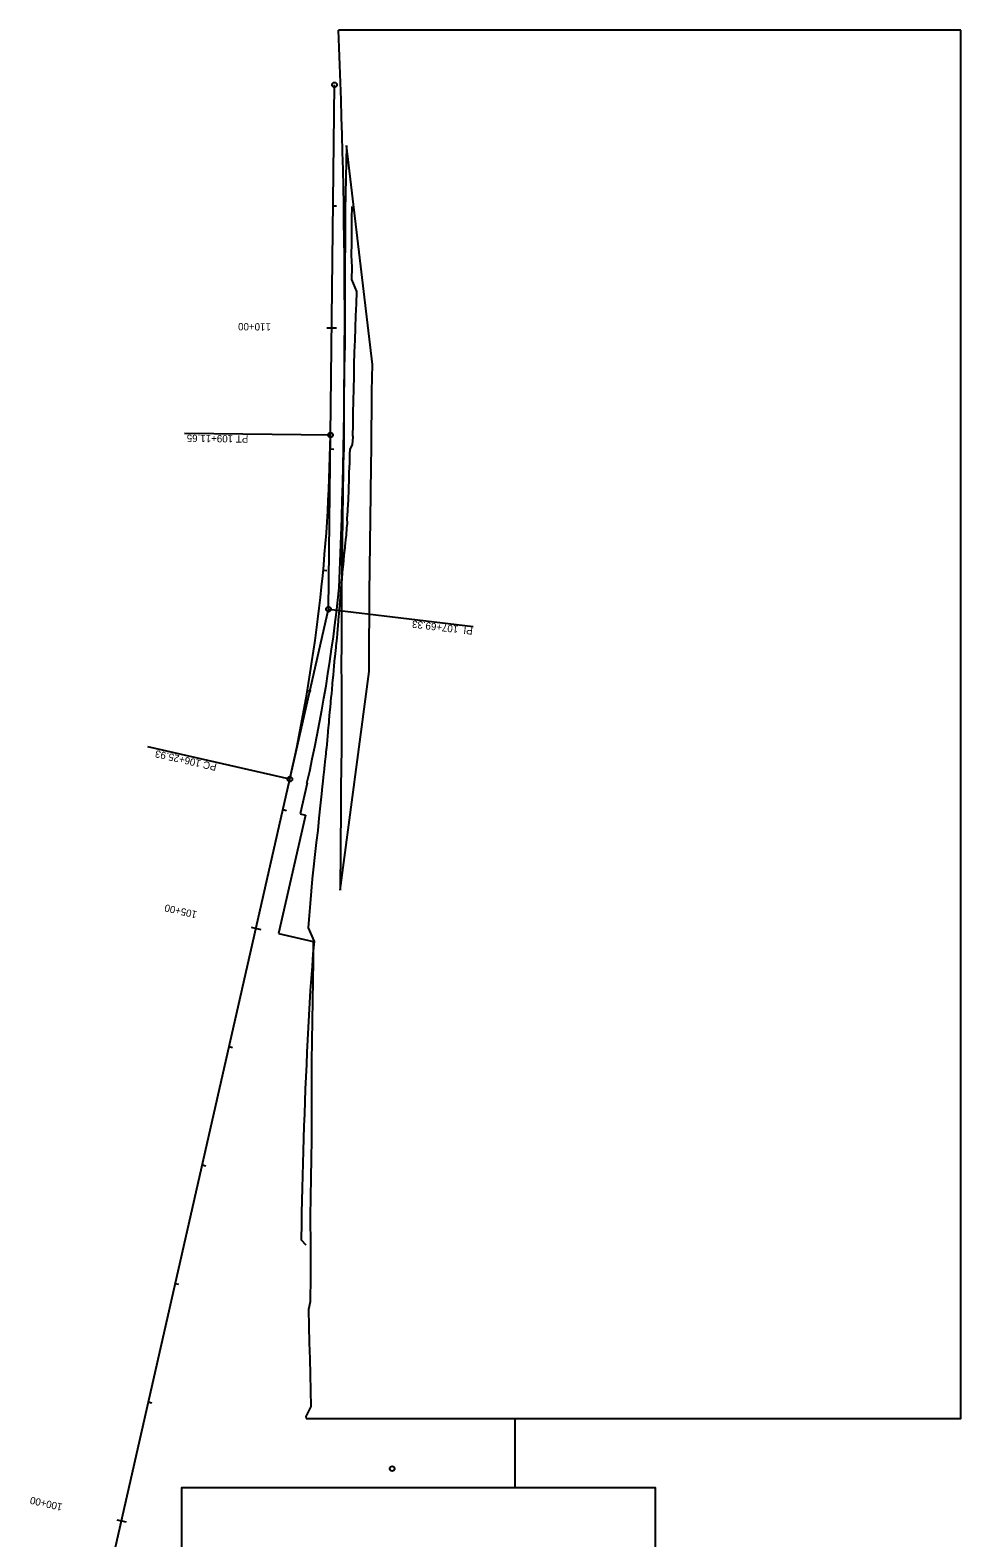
# Model space of a CAD drawing. Extents: x 1710760 to 1713003, y 548603 to 551142.
# Drawn here: x 1712237 to 1713003, y 549901 to 551142 of the extents above; entities that cross this region are included whole.
import ezdxf

# ---------------------------------------------------------------- set-up
doc = ezdxf.new("R2010")
doc.units = 0
for name, color, linetype in [('R_Contours', 7, 'Continuous'), ('R_MOT', 7, 'Continuous'), ('R_No Plot', 7, 'Continuous'), ('R_Point Sym', 7, 'Continuous'), ('R_Proposed Const Limits_Fill', 7, 'Continuous')]:
    doc.layers.add(name, color=color, linetype=linetype)

msp = doc.modelspace()

# ---------------------------------------------------------------- linework, layer by layer
at = {"layer": 'R_Contours'}
for p, q in [((1712482.6, 550665.7), (1712484.2, 550809.1)), ((1712450.8, 550525.8), (1712482.6, 550665.7))]:
    msp.add_line(p, q, dxfattribs=at)
for points in [[(1712489.3, 550997.4), (1712486.3, 550997.4)], [(1712481.2, 550897.4), (1712489.2, 550897.3)], [(1712484.2, 550809.1), (1712364.2, 550810.4)], [(1712487, 550797.3), (1712484, 550797.4)], [(1712481.3, 550697.3), (1712478.3, 550697.6)], [(1712482.6, 550665.7), (1712601.7, 550651.6)], [(1712468.2, 550598), (1712465.2, 550598.5)], [(1712450.8, 550525.8), (1712333.8, 550552.4)], [(1712448, 550499.9), (1712445.1, 550500.5)], [(1712419, 550403.9), (1712426.8, 550402.1)], [(1712403.7, 550304.8), (1712400.8, 550305.5)], [(1712381.6, 550207.3), (1712378.6, 550208)], [(1712359.4, 550109.8), (1712356.5, 550110.5)], [(1712337.3, 550012.3), (1712334.3, 550013)], [(1712308.3, 549916.3), (1712316.1, 549914.5)]]:
    msp.add_lwpolyline(points, dxfattribs=at)
for centre in [(1712487.5, 551097.3), (1712484.2, 550809.1), (1712482.6, 550665.7), (1712450.8, 550525.8), (1712535, 549958.3)]:
    msp.add_circle(centre, 2, dxfattribs=at)
at = {"layer": 'R_MOT'}
for p, q in [((1712518.8, 550867), (1712497.3, 551047.3)), ((1712492.1, 550434.5), (1712516.1, 550614.5))]:
    msp.add_line(p, q, dxfattribs=at)
for points in [[(1712497.3, 551047.3), (1712496.4, 550994.1), (1712496.3, 550970.5), (1712496.1, 550946.9), (1712496.1, 550929.6), (1712496, 550912.4), (1712496, 550897.9), (1712495.9, 550883.5), (1712495.6, 550864.5), (1712495.3, 550845.5), (1712495.2, 550821.9), (1712495.1, 550798.3), (1712494.7, 550785.1), (1712494.6, 550779.9), (1712494.3, 550761.1), (1712494, 550740.6), (1712493.8, 550720.1), (1712493.6, 550699.6), (1712493.4, 550679), (1712493.3, 550664.5), (1712493.2, 550650), (1712493.2, 550635.6), (1712493.1, 550621.1), (1712493.2, 550603.6), (1712493.2, 550586.2), (1712493.3, 550568.8), (1712493.4, 550551.4), (1712493.1, 550535.2), (1712492.8, 550519), (1712492.6, 550502.7), (1712492.1, 550434.5)], [(1712516.1, 550614.5), (1712516.1, 550621), (1712516.4, 550678.9), (1712517.3, 550760.8), (1712517.7, 550784.5), (1712518.1, 550797.8), (1712518.3, 550845.3), (1712518.8, 550867)]]:
    msp.add_lwpolyline(points, dxfattribs=at)
at = {"layer": 'R_No Plot'}
for p, q in [((1713002.9, 551142.3), (1712490.8, 551142.3)), ((1712491.5, 550683.4), (1712491.5, 550683.4)), ((1712464.9, 550522.6), (1712459.2, 550497.3)), ((1712463.6, 550496.3), (1712441.5, 550398.8)), ((1712459.2, 550497.3), (1712463.6, 550496.3)), ((1712441.5, 550398.8), (1712470.1, 550392.3)), ((1712464.3, 549999.7), (1712635.8, 549999.7)), ((1712635.8, 549999.7), (1712635.8, 549942.6)), ((1712636.3, 549942.6), (1712636.3, 549999.7))]:
    msp.add_line(p, q, dxfattribs=at)
for points in [[(1712636.3, 549999.7), (1713002.9, 549999.7), (1713002.9, 551142.3)], [(1712470.1, 550392.3), (1712470.1, 550392.2), (1712469.9, 550376), (1712469.7, 550359.8), (1712469.5, 550343.3), (1712469.2, 550326.8), (1712469, 550310.3), (1712468.7, 550293.8), (1712468.7, 550277.7), (1712468.7, 550261.6), (1712468.6, 550245.4), (1712468.6, 550229.3), (1712468.4, 550213.4), (1712468.1, 550197.6), (1712467.9, 550181.7), (1712467.6, 550165.8), (1712467.7, 550141.1), (1712467.8, 550116.5), (1712467.5, 550095.6), (1712466.2, 550089.2), (1712466.5, 550075.5), (1712466.7, 550061.9), (1712467.1, 550048.8), (1712467.4, 550035.7), (1712467.8, 550022.6), (1712468.1, 550009.5), (1712463.8, 550001.4), (1712464.3, 549999.7)], [(1712635.8, 549942.6), (1712361.6, 549942.6), (1712361.6, 549562.6)], [(1712471.5, 549624.2), (1712751.6, 549624.2), (1712751.6, 549942.6), (1712636.3, 549942.6)]]:
    msp.add_lwpolyline(points, dxfattribs=at)
for centre, radius, start, end in [((1706966.7, 550904.5), 5529.2, 357.7082, 2.4649), ((1711136.1, 550824.3), 1362.6, 347.2066, 354.0638)]:
    msp.add_arc(centre, radius, start, end, dxfattribs=at)
at = {"layer": 'R_Point Sym'}
for p, q in [((1712484.2, 550809.1), (1712487.5, 551097.3)), ((1712246.8, 549627.3), (1712450.8, 550525.8))]:
    msp.add_line(p, q, dxfattribs=at)
msp.add_arc((1711136.1, 550824.3), 1348.1, 347.2066, 359.3498, dxfattribs=at)
at = {"layer": 'R_Proposed Const Limits_Fill'}
msp.add_lwpolyline([(1712464.1, 550142.2), (1712460.4, 550146.5), (1712460.4, 550146.5), (1712460.4, 550148.4), (1712460.6, 550158.6), (1712460.7, 550168.8), (1712460.9, 550179), (1712461.1, 550189.3), (1712461.4, 550199.5), (1712461.7, 550209.6), (1712462, 550219.8), (1712462.3, 550230), (1712462.6, 550240.2), (1712463, 550250.4), (1712463.3, 550260.5), (1712463.7, 550270.7), (1712464.2, 550280.9), (1712464.7, 550291), (1712465.1, 550301.1), (1712465.6, 550311.3), (1712466.1, 550321.4), (1712466.6, 550331.6), (1712467.2, 550341.7), (1712467.9, 550351.8), (1712468.6, 550361.9), (1712469.3, 550372), (1712470.1, 550382), (1712471.1, 550392.1), (1712466, 550403.5), (1712466.9, 550413.5), (1712467.8, 550423.6), (1712468.7, 550433.6), (1712469.5, 550443.7), (1712470.5, 550453.7), (1712471.7, 550463.7), (1712472.8, 550473.7), (1712474.1, 550483.7), (1712475, 550493.7), (1712476, 550503.8), (1712477.1, 550513.8), (1712477.7, 550519.7), (1712478.2, 550523.9), (1712478.6, 550527.4), (1712479.3, 550534.1), (1712479.4, 550535), (1712480.2, 550542.7), (1712480.4, 550544.3), (1712481, 550550.4), (1712481.2, 550551.8), (1712481.4, 550554.4), (1712481.7, 550558), (1712482.3, 550564.6), (1712482.4, 550565.7), (1712483, 550572.7), (1712483, 550573.3), (1712483.2, 550574.8), (1712483.8, 550581), (1712484.2, 550585), (1712484.5, 550588.6), (1712484.6, 550589.9), (1712485.1, 550595.1), (1712485.2, 550596.2), (1712485.9, 550603.8), (1712486, 550605.2), (1712486.6, 550611.5), (1712486.9, 550615.3), (1712487.3, 550619.1), (1712487.9, 550625.5), (1712488, 550626.7), (1712488.8, 550634.2), (1712488.9, 550635.5), (1712489.6, 550641.8), (1712489.9, 550645.6), (1712490.2, 550649.4), (1712490.8, 550655.7), (1712490.9, 550657), (1712491.5, 550664.6), (1712491.6, 550665.8), (1712492.1, 550672.2), (1712492.4, 550675.9), (1712492.7, 550679.8), (1712493.2, 550686), (1712493.3, 550687.4), (1712493.7, 550691.5), (1712494.1, 550694.9), (1712494.2, 550696.1), (1712494.8, 550702.5), (1712495.1, 550706.2), (1712495.5, 550710.1), (1712496.2, 550716.2), (1712496.4, 550717.7), (1712497.2, 550725.2), (1712497.3, 550726.3), (1712497.8, 550732.8), (1712498.1, 550736.4), (1712498, 550740.4), (1712498.6, 550746.5), (1712498.6, 550748), (1712499, 550755.6), (1712499.1, 550756.6), (1712499.2, 550763.2), (1712499.3, 550766.7), (1712499.5, 550770.8), (1712499.7, 550776.8), (1712499.7, 550778.4), (1712500.1, 550786), (1712500.1, 550787), (1712500.1, 550793.7), (1712500.3, 550797.1), (1712502.2, 550801.2), (1712502.8, 550807.2), (1712502.7, 550808.8), (1712502.8, 550817.2), (1712502.9, 550827.2), (1712503.2, 550837.2), (1712503.3, 550847.2), (1712503.6, 550857.2), (1712503.8, 550867.2), (1712504.1, 550877.2), (1712504.4, 550887.2), (1712504.7, 550897.2), (1712505, 550907.2), (1712505.6, 550917.2), (1712505.9, 550927.2), (1712501.7, 550937.2), (1712502, 550947.2), (1712501.5, 550957.2), (1712501.7, 550967.2), (1712501.7, 550977.2), (1712501.7, 550987.2), (1712502, 550997.2)], dxfattribs=at)

# ---------------------------------------------------------------- texts
at = {"layer": 'R_Contours'}
for s, rotation, p in [('110+00', 179.3498, (1712435.2, 550901)), ('PT 109+11.65', 179.3498, (1712416.6, 550808.8)), ('PI  107+69.33', 173.2782, (1712601.6, 550650.6)), ('PC 106+25.93', 167.2066, (1712391, 550538.4)), ('105+00', 167.2066, (1712374.8, 550417)), ('100+00', 167.2066, (1712264.1, 549929.4))]:
    msp.add_text(s, height=6, rotation=rotation, dxfattribs=at).set_placement(p)

doc.saveas('drawing.dxf')
